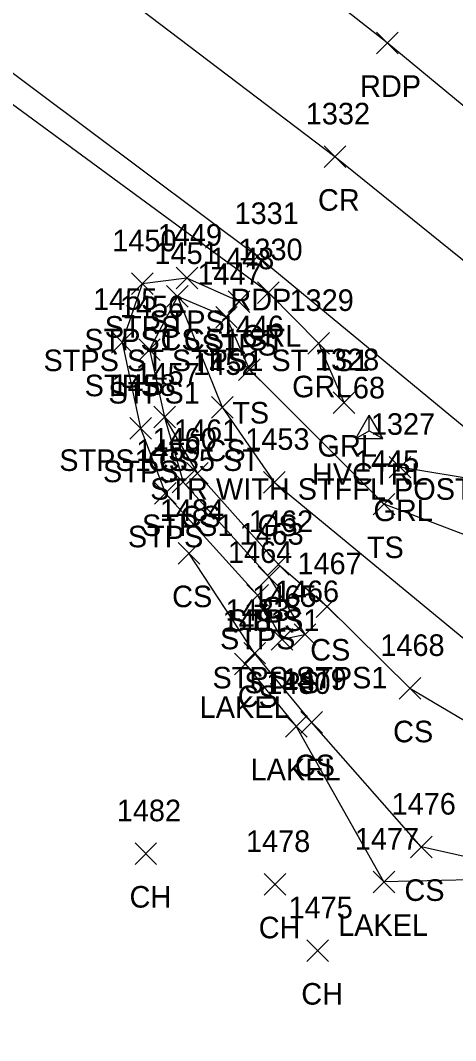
# Model space of a CAD drawing. Extents: x 1401404 to 1403982, y 557481 to 559873.
# Drawn here: x 1403022 to 1403062.3, y 558734 to 558828.6 of the extents above; entities that cross this region are included whole.
import ezdxf

# ---------------------------------------------------------------- set-up
doc = ezdxf.new("R2010")
doc.units = 0
for name, color, linetype in [('C_A', 7, 'Continuous'), ('C_I', 7, 'Continuous'), ('CPSM', 7, 'Continuous'), ('L_A', 7, 'Continuous'), ('L_I', 7, 'Continuous'), ('L_TIC', 7, 'Continuous'), ('LAWE', 7, 'Continuous'), ('LBF', 7, 'Continuous'), ('LELB', 7, 'Continuous'), ('P_A', 7, 'Continuous'), ('P_I', 7, 'Continuous'), ('P_TIC', 7, 'Continuous'), ('PET', 7, 'Continuous'), ('PRC', 7, 'Continuous'), ('R_A', 7, 'Continuous'), ('R_C', 7, 'Continuous'), ('R_I', 7, 'Continuous'), ('R_TIC', 7, 'Continuous'), ('RGR', 7, 'Continuous')]:
    doc.layers.add(name, color=color, linetype=linetype)

msp = doc.modelspace()

# ---------------------------------------------------------------- linework, layer by layer
at = {"layer": 'CPSM'}
for p, q in [((1403053.034, 558789.821), (1403054.284, 558791.986)), ((1403055.534, 558789.821), (1403054.284, 558791.986)), ((1403054.284, 558790.543), (1403054.284, 558791.986)), ((1403053.034, 558789.821), (1403054.284, 558790.543)), ((1403054.284, 558790.543), (1403054.284, 558790.543)), ((1403054.284, 558790.543), (1403055.534, 558789.821)), ((1403053.034, 558789.821), (1403055.534, 558789.821))]:
    msp.add_line(p, q, dxfattribs=at)
at = {"layer": 'L_TIC'}
for points in [[(1403036.399, 558803.694), (1403038.399, 558805.694)], [(1403038.399, 558803.694), (1403036.399, 558805.694)], [(1403032.266, 558803.174), (1403034.266, 558805.174)], [(1403034.266, 558803.174), (1403032.266, 558805.174)], [(1403035.52, 558801.994), (1403037.52, 558803.994)], [(1403037.52, 558801.994), (1403035.52, 558803.994)], [(1403035.52, 558801.994), (1403037.52, 558803.994)], [(1403037.52, 558801.994), (1403035.52, 558803.994)], [(1403041.226, 558801.513), (1403043.226, 558803.513)], [(1403043.226, 558801.513), (1403041.226, 558803.513)], [(1403040.062, 558800.071), (1403042.062, 558802.071)], [(1403042.062, 558800.071), (1403040.062, 558802.071)], [(1403040.062, 558800.071), (1403042.062, 558802.071)], [(1403042.062, 558800.071), (1403040.062, 558802.071)], [(1403040.062, 558800.071), (1403042.062, 558802.071)], [(1403042.062, 558800.071), (1403040.062, 558802.071)], [(1403030.404, 558797.744), (1403032.404, 558799.744)], [(1403032.404, 558797.744), (1403030.404, 558799.744)], [(1403032.933, 558797.068), (1403034.933, 558799.068)], [(1403034.933, 558797.068), (1403032.933, 558799.068)], [(1403042.183, 558795.215), (1403044.183, 558797.215)], [(1403044.183, 558795.215), (1403042.183, 558797.215)], [(1403039.675, 558791.723), (1403041.675, 558793.723)], [(1403041.675, 558791.723), (1403039.675, 558793.723)], [(1403034.333, 558790.822), (1403036.333, 558792.822)], [(1403036.333, 558790.822), (1403034.333, 558792.822)], [(1403034.333, 558790.822), (1403036.333, 558792.822)], [(1403036.333, 558790.822), (1403034.333, 558792.822)], [(1403032.104, 558789.779), (1403034.104, 558791.779)], [(1403034.104, 558789.779), (1403032.104, 558791.779)], [(1403036.045, 558784.79), (1403038.045, 558786.79)], [(1403038.045, 558784.79), (1403036.045, 558786.79)], [(1403037.373, 558785.596), (1403039.373, 558787.596)], [(1403039.373, 558785.596), (1403037.373, 558787.596)], [(1403044.494, 558784.776), (1403046.494, 558786.776)], [(1403046.494, 558784.776), (1403044.494, 558786.776)], [(1403034.412, 558783.745), (1403036.412, 558785.745)], [(1403036.412, 558783.745), (1403034.412, 558785.745)], [(1403054.653, 558782.747), (1403056.653, 558784.747)], [(1403056.653, 558782.747), (1403054.653, 558784.747)], [(1403036.589, 558778.198), (1403038.589, 558780.198)], [(1403038.589, 558778.198), (1403036.589, 558780.198)], [(1403044.88, 558777.163), (1403046.88, 558779.163)], [(1403046.88, 558777.163), (1403044.88, 558779.163)], [(1403044.006, 558775.99), (1403046.006, 558777.99)], [(1403046.006, 558775.99), (1403044.006, 558777.99)], [(1403042.943, 558774.297), (1403044.943, 558776.297)], [(1403044.943, 558774.297), (1403042.943, 558776.297)], [(1403049.376, 558773.251), (1403051.376, 558775.251)], [(1403051.376, 558773.251), (1403049.376, 558775.251)], [(1403047.334, 558770.669), (1403049.334, 558772.669)], [(1403049.334, 558770.669), (1403047.334, 558772.669)], [(1403047.334, 558770.669), (1403049.334, 558772.669)], [(1403049.334, 558770.669), (1403047.334, 558772.669)], [(1403045.2, 558770.222), (1403047.2, 558772.222)], [(1403047.2, 558770.222), (1403045.2, 558772.222)], [(1403042.664, 558768.94), (1403044.664, 558770.94)], [(1403044.664, 558768.94), (1403042.664, 558770.94)], [(1403041.819, 558767.94), (1403043.819, 558769.94)], [(1403043.819, 558767.94), (1403041.819, 558769.94)], [(1403057.051, 558765.679), (1403059.051, 558767.679)], [(1403059.051, 558765.679), (1403057.051, 558767.679)], [(1403046.531, 558762.161), (1403048.531, 558764.161)], [(1403048.531, 558762.161), (1403046.531, 558764.161)], [(1403047.949, 558762.532), (1403049.949, 558764.532)], [(1403049.949, 558762.532), (1403047.949, 558764.532)], [(1403058.101, 558750.979), (1403060.101, 558752.979)], [(1403060.101, 558750.979), (1403058.101, 558752.979)], [(1403032.597, 558750.361), (1403034.597, 558752.361)], [(1403034.597, 558750.361), (1403032.597, 558752.361)], [(1403044.562, 558747.514), (1403046.562, 558749.514)], [(1403046.562, 558747.514), (1403044.562, 558749.514)], [(1403054.639, 558747.741), (1403056.639, 558749.741)], [(1403056.639, 558747.741), (1403054.639, 558749.741)], [(1403048.502, 558741.369), (1403050.502, 558743.369)], [(1403050.502, 558741.369), (1403048.502, 558743.369)]]:
    msp.add_lwpolyline(points, dxfattribs=at)
at = {"layer": 'LAWE'}
msp.add_lwpolyline([(1403238.681, 558611.558), (1403231.812, 558615.037), (1403202.572, 558639.469), (1403173.172, 558667.726), (1403127.979, 558695.57), (1403090.177, 558721.426), (1403068.989, 558749.068), (1403055.639, 558748.741), (1403047.531, 558763.161), (1403042.819, 558768.94)], dxfattribs=at)
at = {"layer": 'LBF'}
for points in [[(1403041.062, 558801.071), (1403042.226, 558802.513), (1403037.399, 558804.694), (1403033.266, 558804.174), (1403031.404, 558798.744), (1403033.104, 558790.779), (1403035.412, 558784.745), (1403043.943, 558775.297), (1403046.2, 558771.222), (1403048.334, 558771.669)], [(1403041.062, 558801.071), (1403036.52, 558802.994), (1403033.933, 558798.068), (1403035.333, 558791.822), (1403037.045, 558785.79), (1403045.006, 558776.99), (1403048.334, 558771.669)]]:
    msp.add_lwpolyline(points, dxfattribs=at)
at = {"layer": 'LELB'}
for points in [[(1403036.52, 558802.994), (1403040.675, 558792.723), (1403045.494, 558785.776), (1403068.31, 558766.926)], [(1403567.19, 558568.672), (1403521.327, 558570.05), (1403484.768, 558571.485), (1403436.828, 558574.711), (1403390.353, 558579.879), (1403360.169, 558585.19), (1403345.928, 558587.285), (1403333.514, 558592.26), (1403317.515, 558600.618), (1403299.002, 558608.828), (1403282.939, 558617.965), (1403248.094, 558638.933), (1403217.119, 558660.936), (1403185.325, 558684.7), (1403148.792, 558715.456), (1403112.062, 558744.487), (1403074.233, 558776.659), (1403055.653, 558783.747), (1403043.183, 558796.215), (1403041.062, 558801.071)], [(1403035.333, 558791.822), (1403038.373, 558786.596), (1403045.88, 558778.163), (1403050.376, 558774.251), (1403058.051, 558766.679), (1403067.502, 558761.109), (1403071.884, 558756.662)], [(1403083.095, 558739.17), (1403070.512, 558749.441), (1403059.101, 558751.979), (1403048.949, 558763.532), (1403043.664, 558769.94), (1403037.589, 558779.198)]]:
    msp.add_lwpolyline(points, dxfattribs=at)
at = {"layer": 'P_TIC'}
for points in [[(1403054.947, 558825.49), (1403056.947, 558827.49)], [(1403056.947, 558825.49), (1403054.947, 558827.49)], [(1403050.101, 558814.937), (1403052.101, 558816.937)], [(1403052.101, 558814.937), (1403050.101, 558816.937)], [(1403042.936, 558805.704), (1403044.936, 558807.704)], [(1403044.936, 558805.704), (1403042.936, 558807.704)]]:
    msp.add_lwpolyline(points, dxfattribs=at)
at = {"layer": 'PET'}
for points in [[(1403164.555, 558736.666), (1403129.248, 558765.781), (1403090.497, 558797.896), (1403080.901, 558805.872), (1403055.947, 558826.49), (1403037.693, 558840.863), (1403021.818, 558852), (1403010.766, 558860.563), (1402965.567, 558891.006), (1402927.929, 558913.53), (1402884.611, 558936.362), (1402848.098, 558956.632), (1402812.557, 558974.835), (1402775.42, 558993.623)], [(1403567.323, 558571.161), (1403521.055, 558571.892), (1403485.08, 558573.953), (1403437.345, 558577.288), (1403390.926, 558583.548), (1403361.613, 558591.03), (1403321.823, 558602.545), (1403283.736, 558620.332), (1403244.193, 558645.3), (1403219.218, 558663.606), (1403205.442, 558672.119), (1403186.056, 558688.409), (1403150.644, 558718.107), (1403114.176, 558748.056), (1403076.198, 558780.032), (1403043.936, 558806.704), (1402997.13, 558841.767), (1402954.247, 558870.687), (1402915.87, 558893.532), (1402876.179, 558915.415), (1402801.328, 558955.205), (1402766.491, 558972.95)]]:
    msp.add_lwpolyline(points, dxfattribs=at)
at = {"layer": 'PRC'}
msp.add_lwpolyline([(1403567.874, 558582.773), (1403521.719, 558584.551), (1403486.229, 558585.007), (1403438.972, 558588.433), (1403393.102, 558594.896), (1403360.826, 558602.705), (1403288.915, 558631.603), (1403250.295, 558655.214), (1403225.89, 558672.347), (1403193.368, 558698.042), (1403157.152, 558726.964), (1403121.948, 558757.263), (1403083.224, 558789.984), (1403051.101, 558815.937), (1403004.274, 558851.49), (1402960.213, 558880.82), (1402921.635, 558903.817), (1402881.318, 558926.058), (1402807.323, 558964.726), (1402770.827, 558983.445)], dxfattribs=at)
at = {"layer": 'R_TIC'}
for points in [[(1403043.942, 558802.349), (1403045.942, 558804.349)], [(1403045.942, 558802.349), (1403043.942, 558804.349)], [(1403048.602, 558797.647), (1403050.602, 558799.647)], [(1403050.602, 558797.647), (1403048.602, 558799.647)], [(1403050.947, 558792.152), (1403052.947, 558794.152)], [(1403052.947, 558792.152), (1403050.947, 558794.152)], [(1403056.128, 558786.174), (1403058.128, 558788.174)], [(1403058.128, 558786.174), (1403056.128, 558788.174)]]:
    msp.add_lwpolyline(points, dxfattribs=at)
at = {"layer": 'RGR'}
for points in [[(1403051.947, 558793.152), (1403049.602, 558798.647), (1403044.942, 558803.349), (1402995.407, 558839.767), (1402953.151, 558868.547), (1402914.608, 558891.049)], [(1403343.042, 558588.832), (1403321.634, 558601.07), (1403283.23, 558619.584), (1403243.098, 558643.516), (1403218.12, 558661.744), (1403185.478, 558687.648), (1403149.871, 558716.896), (1403113.349, 558746.324), (1403075.032, 558778.374), (1403064.917, 558785.886), (1403057.128, 558787.174)]]:
    msp.add_lwpolyline(points, dxfattribs=at)

# ---------------------------------------------------------------- texts
at = {"layer": 'C_A'}
msp.add_text('HVCTRL', height=2, dxfattribs=at).set_placement((1403048.977, 558785.543))
at = {"layer": 'C_I'}
msp.add_text('68', height=2, dxfattribs=at).set_placement((1403052.772, 558793.543))
at = {"layer": 'L_A'}
for s, p in [('STPS', (1403029.786, 558799.174)), ('STPS', (1403033.918, 558799.694)), ('STPS1 CS1 ST', (1403027.898, 558797.994)), ('CS', (1403034.961, 558797.994)), ('STPS', (1403038.745, 558797.513)), ('STPS ST STPS1 ST TS1', (1403024.118, 558796.071)), ('STPS ST STPS1 ST TS1', (1403024.118, 558796.071)), ('TS', (1403039.472, 558796.071)), ('STPS', (1403027.924, 558793.744)), ('STPS1', (1403030.121, 558793.068)), ('TS', (1403041.593, 558791.215)), ('CS', (1403039.116, 558787.723)), ('STPS1 CS5 ST', (1403025.577, 558786.822)), ('CS', (1403033.774, 558786.822)), ('STPS', (1403029.623, 558785.779)), ('CS', (1403036.814, 558781.596)), ('STPS1', (1403033.234, 558780.79)), ('CS', (1403043.935, 558780.776)), ('STPS', (1403031.931, 558779.745)), ('TS', (1403054.063, 558778.747)), ('CS', (1403036.03, 558774.198)), ('CS', (1403044.321, 558773.163)), ('STPS1', (1403041.195, 558771.99)), ('STPS', (1403040.463, 558770.297)), ('CS', (1403048.817, 558769.251)), ('STPS STPS1', (1403039.767, 558766.669)), ('STPS STPS1', (1403039.767, 558766.669)), ('STPS', (1403042.719, 558766.222)), ('CS', (1403042.105, 558764.94)), ('LAKEL', (1403038.583, 558763.94)), ('CS', (1403056.492, 558761.679)), ('CS', (1403047.39, 558758.532)), ('LAKEL', (1403043.294, 558758.161)), ('CS', (1403057.542, 558746.979)), ('CH', (1403032.086, 558746.361)), ('CH', (1403044.05, 558743.514)), ('LAKEL', (1403051.403, 558743.741)), ('CH', (1403047.99, 558737.369))]:
    msp.add_text(s, height=2, dxfattribs=at).set_placement(p)
at = {"layer": 'L_I'}
for s, p in [('1449', (1403034.698, 558807.694)), ('1450', (1403030.487, 558807.174)), ('1451', (1403034.394, 558805.994)), ('1451', (1403034.394, 558805.994)), ('1448', (1403039.533, 558805.513)), ('1447', (1403038.37, 558804.071)), ('1447', (1403038.37, 558804.071)), ('1447', (1403038.37, 558804.071)), ('1455', (1403028.711, 558801.744)), ('1456', (1403031.184, 558801.068)), ('1446', (1403040.435, 558799.215)), ('1452', (1403037.982, 558795.723)), ('1457', (1403032.64, 558794.822)), ('1457', (1403032.64, 558794.822)), ('1458', (1403030.411, 558793.779)), ('1461', (1403036.199, 558789.596)), ('1460', (1403034.219, 558788.79)), ('1453', (1403042.801, 558788.776)), ('1459', (1403032.711, 558787.745)), ('1445', (1403052.961, 558786.747)), ('1484', (1403034.896, 558782.198)), ('1462', (1403043.14, 558781.163)), ('1463', (1403042.266, 558779.99)), ('1464', (1403041.203, 558778.297)), ('1467', (1403047.636, 558777.251)), ('1466', (1403045.539, 558774.669)), ('1466', (1403045.539, 558774.669)), ('1465', (1403043.46, 558774.222)), ('1483', (1403040.971, 558772.94)), ('1481', (1403040.693, 558771.94)), ('1468', (1403055.311, 558769.679)), ('1480', (1403044.751, 558766.161)), ('1479', (1403046.248, 558766.532)), ('1476', (1403056.353, 558754.979)), ('1482', (1403030.904, 558754.361)), ('1477', (1403052.946, 558751.741)), ('1478', (1403042.869, 558751.514)), ('1475', (1403046.809, 558745.369))]:
    msp.add_text(s, height=2, dxfattribs=at).set_placement(p)
at = {"layer": 'P_A'}
for s, p in [('RDP', (1403053.435, 558821.49)), ('CR', (1403049.534, 558810.937)), ('RDP', (1403041.424, 558801.704))]:
    msp.add_text(s, height=2, dxfattribs=at).set_placement(p)
at = {"layer": 'P_I'}
for s, p in [('1332', (1403048.408, 558818.937)), ('1331', (1403041.81, 558809.704))]:
    msp.add_text(s, height=2, dxfattribs=at).set_placement(p)
at = {"layer": 'R_A'}
for p in [(1403042.485, 558798.349), (1403047.146, 558793.647), (1403049.49, 558788.152), (1403054.671, 558782.174)]:
    msp.add_text('GRL', height=2, dxfattribs=at).set_placement(p)
at = {"layer": 'R_C'}
msp.add_text('STR WITH STFFL POSTS', height=2, dxfattribs=at).set_placement((1403033.994, 558784.152))
at = {"layer": 'R_I'}
for s, p in [('1330', (1403042.162, 558806.349)), ('1329', (1403046.902, 558801.647)), ('1328', (1403049.254, 558796.152)), ('1327', (1403054.435, 558790.174))]:
    msp.add_text(s, height=2, dxfattribs=at).set_placement(p)

doc.saveas('drawing.dxf')
